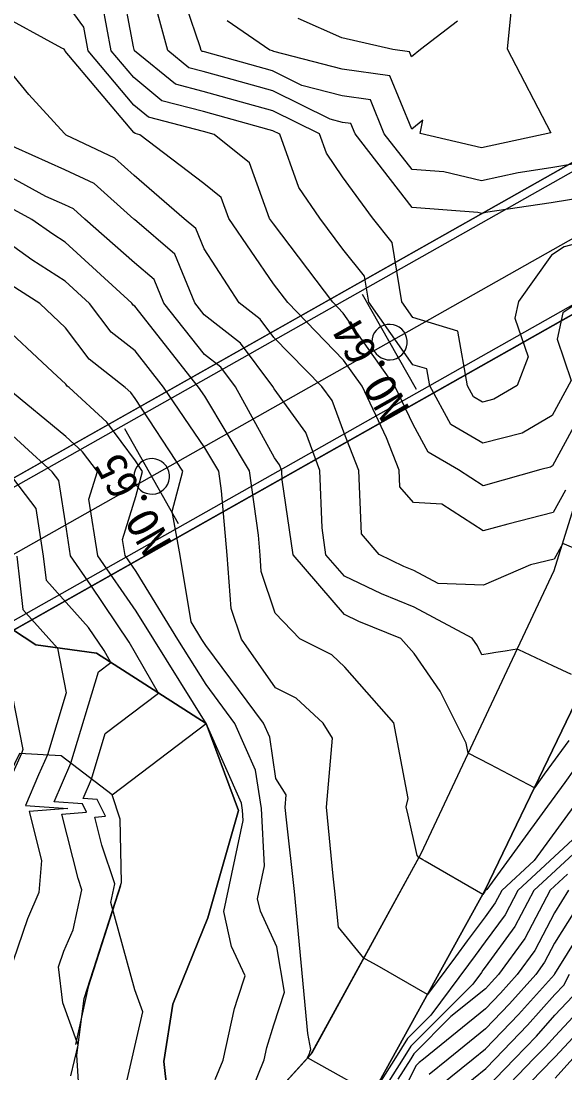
# Model space of a CAD drawing. Extents: x 42655 to 43811, y -141820 to -141156.
# Drawn here: x 42836.1 to 42875.9, y -141619.1 to -141542.1 of the extents above; entities that cross this region are included whole.
import ezdxf

# ---------------------------------------------------------------- set-up
doc = ezdxf.new("R2010")
doc.units = 0
for name, color, linetype in [('D-BMK-HTXT_1', 7, 'Continuous'), ('D-BMK_1', 7, 'Continuous'), ('D-STR-STR2トンネル', 7, 'Continuous'), ('ZE_HICN', 7, 'Continuous'), ('ZE_LWCN', 7, 'Continuous'), ('地形', 7, 'Continuous'), ('現況道路ﾊｯﾁ', 7, 'Continuous'), ('着色', 7, 'Continuous')]:
    doc.layers.add(name, color=color, linetype=linetype)

msp = doc.modelspace()

# ---------------------------------------------------------------- linework, layer by layer
at = {"layer": 'D-BMK-HTXT_1'}
for p, q in [((42865.022, -141569.047), (42861.089, -141562.081)), ((42847.607, -141578.881), (42843.674, -141571.915))]:
    msp.add_line(p, q, dxfattribs=at)
for points in [[(42861.755, -141565.564), (42861.776, -141565.796), (42861.838, -141566.021), (42861.939, -141566.231), (42862.076, -141566.419), (42862.245, -141566.58), (42862.439, -141566.709), (42862.654, -141566.8), (42862.881, -141566.852), (42863.114, -141566.862), (42863.345, -141566.831), (42863.566, -141566.759), (42863.772, -141566.649), (42863.954, -141566.503), (42864.107, -141566.328), (42864.227, -141566.128), (42864.309, -141565.91), (42864.35, -141565.68), (42864.35, -141565.447), (42864.309, -141565.218), (42864.227, -141565), (42864.107, -141564.8), (42863.954, -141564.624), (42863.772, -141564.479), (42863.566, -141564.368), (42863.345, -141564.296), (42863.114, -141564.265), (42862.881, -141564.276), (42862.654, -141564.327), (42862.439, -141564.419), (42862.245, -141564.547), (42862.076, -141564.708), (42861.939, -141564.897), (42861.838, -141565.107), (42861.776, -141565.332), (42861.755, -141565.564)], [(42844.34, -141575.398), (42844.361, -141575.63), (42844.423, -141575.855), (42844.525, -141576.065), (42844.661, -141576.254), (42844.83, -141576.415), (42845.024, -141576.543), (42845.239, -141576.635), (42845.466, -141576.687), (42845.699, -141576.697), (42845.93, -141576.666), (42846.151, -141576.594), (42846.357, -141576.483), (42846.539, -141576.338), (42846.692, -141576.162), (42846.812, -141575.962), (42846.894, -141575.744), (42846.935, -141575.515), (42846.935, -141575.282), (42846.894, -141575.052), (42846.812, -141574.834), (42846.692, -141574.634), (42846.539, -141574.459), (42846.357, -141574.313), (42846.151, -141574.203), (42845.93, -141574.131), (42845.699, -141574.1), (42845.466, -141574.11), (42845.239, -141574.162), (42845.024, -141574.254), (42844.83, -141574.382), (42844.661, -141574.543), (42844.524, -141574.732), (42844.423, -141574.942), (42844.361, -141575.166), (42844.34, -141575.398)]]:
    msp.add_lwpolyline(points, dxfattribs=at)
at = {"layer": 'D-BMK_1'}
msp.add_line((42932.715, -141526.226), (42777.191, -141614.053), dxfattribs=at)
at = {"layer": 'D-STR-STR2トンネル'}
for p, q in [((43087.053, -141433.469), (42774.793, -141609.807)), ((43087.348, -141433.992), (42775.088, -141610.33)), ((43091.527, -141441.393), (42779.268, -141617.731)), ((43091.822, -141441.915), (42779.563, -141618.253))]:
    msp.add_line(p, q, dxfattribs=at)
at = {"layer": 'ZE_HICN'}
msp.add_line((42842.734, -141598.733), (42849.632, -141593.502), dxfattribs=at)
for points in [[(42877.437, -141562.302), (42875.739, -141563.417), (42875.328, -141565.358), (42876.367, -141568.384), (42874.968, -141570.947), (42872.77, -141572.236), (42869.889, -141572.965), (42867.547, -141571.596), (42866.019, -141568.775), (42865.802, -141567.532), (42864.774, -141567.223), (42861.53, -141562.633), (42861.223, -141560.736), (42859.646, -141558.752), (42857.952, -141556.487), (42856.404, -141554.233), (42855.016, -141550.338), (42854.518, -141550.092), (42854.25, -141550.017), (42849.423, -141548.681), (42846.39, -141547.884), (42844.323, -141546.185), (42842.674, -141544.233), (42842.03, -141540.82)], [(42864.523, -141544.306), (42863.291, -141544.137), (42859.574, -141543.274), (42856.373, -141541.876)], [(42868.04, -141542.05), (42865.319, -141544.127), (42864.669, -141544.662), (42864.523, -141544.306)], [(42876.2, -141594.736), (42874.395, -141597.214), (42873.664, -141598.218), (42870.42, -141596.508), (42868.817, -141595.681), (42868.674, -141594.935), (42866.773, -141591.136), (42864.873, -141588.369), (42863.889, -141587.273), (42860.818, -141586.022), (42859.771, -141585.519), (42855.989, -141581.147), (42855.189, -141575.657), (42855.165, -141574.988), (42854.999, -141574.544), (42854.629, -141574.031), (42851.772, -141568.841), (42850.699, -141567.406), (42849.506, -141566.468), (42846.522, -141562.703), (42845.817, -141560.98), (42844.386, -141559.759), (42840.752, -141556.567), (42839.906, -141555.812), (42839.278, -141555.517), (42837.885, -141554.896), (42834.178, -141552.887)], [(42850.288, -141619.563), (42850.861, -141618.147), (42851.708, -141614.377), (42851.943, -141613.619), (42852.476, -141611.977), (42851.489, -141609.824), (42850.927, -141607.267), (42852.327, -141600.589), (42852.286, -141599.835), (42852.211, -141599.331), (42849.632, -141593.502), (42845.787, -141587.357), (42844.505, -141585.27), (42841.693, -141581.214), (42841.042, -141577.069), (42841.661, -141575.051), (42840.572, -141573.591), (42839.357, -141572.475), (42835.032, -141568.919)], [(42876.084, -141604.543), (42874.823, -141605.71), (42872.97, -141609.245), (42871.028, -141611.89), (42870.531, -141612.446), (42870.076, -141612.919), (42867.559, -141614.966), (42864.846, -141617.686), (42864.612, -141618.056), (42863.669, -141619.548)], [(42870.11, -141620.228), (42872.217, -141618.047), (42873.815, -141616.386), (42875.173, -141614.869), (42876.489, -141613.466)]]:
    msp.add_lwpolyline(points, dxfattribs=at)
at = {"layer": 'ZE_LWCN'}
for points in [[(42884.992, -141538.265), (42880.028, -141544.059), (42879.977, -141544.103), (42878.085, -141549.772), (42880.914, -141549.94), (42879.966, -141551.625), (42876.746, -141552.494), (42874.883, -141552.802), (42872.485, -141553.163), (42869.8, -141553.746), (42867.03, -141553.094), (42864.707, -141552.914), (42862.677, -141550.302), (42861.657, -141547.811), (42859.594, -141547.528), (42856.645, -141546.763), (42854.497, -141545.7), (42849.497, -141544.316), (42849.402, -141544.289), (42849.343, -141544.274), (42849.256, -141544.202), (42849.186, -141543.942), (42847.18, -141538.049)], [(42889.073, -141538.444), (42885.428, -141543.358), (42885.018, -141543.867), (42884.874, -141544.036), (42882.294, -141546.317), (42881.298, -141549.299), (42882.787, -141549.387), (42879.979, -141554.376), (42878.62, -141554.743), (42874.895, -141555.36), (42870.098, -141556.081), (42869.811, -141556.144), (42869.514, -141556.074), (42864.72, -141555.703), (42860.53, -141550.312), (42860.223, -141549.563), (42859.603, -141549.478), (42858.716, -141549.248), (42854.504, -141547.164), (42851.081, -141546.216), (42849.409, -141545.753), (42848.359, -141545.477), (42846.821, -141544.214), (42845.582, -141539.619)], [(42879.959, -141557.507), (42875.841, -141558.595), (42874.913, -141559.205), (42872.504, -141562.582), (42872.245, -141563.805), (42873.223, -141566.652), (42872.414, -141568.745), (42870.698, -141569.751), (42869.875, -141569.959), (42869.206, -141569.568), (42868.769, -141568.762), (42868.071, -141564.758), (42864.758, -141563.76), (42863.953, -141562.622), (42863.247, -141558.262), (42861.822, -141556.469), (42859.622, -141553.453), (42858.444, -141551.738), (42857.94, -141550.324), (42854.511, -141548.628), (42852.665, -141548.117), (42849.416, -141547.217), (42847.374, -141546.681), (42844.387, -141544.225), (42844.313, -141543.949), (42843.405, -141539.139)], [(42878.717, -141567.803), (42874.985, -141574.637), (42874.841, -141574.722), (42874.138, -141574.899), (42869.904, -141576.079), (42868.117, -141574.928), (42865.888, -141573.625), (42864.795, -141571.605), (42863.455, -141568.787), (42859.668, -141563.434), (42858.905, -141562.645), (42854.549, -141556.899), (42854.278, -141556.504), (42852.798, -141552.445), (42850.21, -141550.36), (42849.43, -141550.145), (42845.406, -141549.088), (42844.332, -141548.206), (42840.984, -141544.241), (42840.656, -141542.501), (42839.208, -141540.479)], [(42875.952, -141576.41), (42875.046, -141578.055), (42871.719, -141578.891), (42869.919, -141579.392), (42866.893, -141577.441), (42864.821, -141577.313), (42863.821, -141576.153), (42863.775, -141574.948), (42862.842, -141572.582), (42861.044, -141568.798), (42859.684, -141566.876), (42855.601, -141562.661), (42854.57, -141561.301), (42851.285, -141556.518), (42850.724, -141554.98), (42849.447, -141553.952), (42844.78, -141550.386), (42844.421, -141550.292), (42844.342, -141550.226), (42839.293, -141544.249), (42839.281, -141544.182), (42839.225, -141544.104), (42839.045, -141544.032), (42834.124, -141541.355)], [(42871.942, -141541.431), (42871.67, -141544.098), (42874.871, -141550.245), (42869.788, -141551.348), (42865.294, -141550.29), (42865.494, -141549.316), (42864.694, -141549.974), (42863.09, -141546.058), (42859.585, -141545.578), (42854.573, -141544.277), (42854.49, -141544.236), (42854.282, -141544.179), (42851.163, -141542.048)], [(42879.424, -141581.859), (42875.741, -141580.307), (42875.11, -141581.452), (42873.391, -141581.884), (42869.938, -141583.369), (42866.612, -141583.232), (42864.844, -141582.29), (42864.114, -141581.992), (42862.295, -141581.117), (42860.994, -141579.609), (42860.817, -141574.962), (42859.709, -141572.152), (42858.847, -141569.839), (42858.105, -141568.812), (42854.588, -141565.227), (42853.582, -141563.882), (42852.051, -141562.677), (42849.47, -141558.732), (42848.865, -141557.253), (42848.022, -141556.533), (42844.356, -141553.356), (42842.945, -141552.097), (42839.363, -141550.411), (42839.254, -141550.286), (42836.628, -141547.425), (42834.138, -141544.405)], [(42876.394, -141589.901), (42875.027, -141589.264), (42872.529, -141588.095), (42872.413, -141588.046), (42872.097, -141588.097), (42871.532, -141588.189), (42870.837, -141588.301), (42870.436, -141588.366), (42869.821, -141588.465), (42869.493, -141587.81), (42869.108, -141587.248), (42864.857, -141584.981), (42862.466, -141584.007), (42859.758, -141582.705), (42858.4, -141581.136), (42858.113, -141579.165), (42857.961, -141574.975), (42856.923, -141572.191), (42854.606, -141568.98), (42854.523, -141568.828), (42852.14, -141565.644), (42849.492, -141563.561), (42848.804, -141562.692), (42847.341, -141559.117), (42844.371, -141556.582), (42844.335, -141556.551), (42841.425, -141553.955), (42839.266, -141552.938), (42834.473, -141550.804)], [(42877.228, -141595.969), (42875.889, -141597.809), (42874.622, -141599.548), (42870.181, -141605.647), (42870.089, -141605.732), (42870.071, -141605.767), (42870.042, -141605.806), (42869.881, -141606.024), (42865.66, -141603.57), (42865.499, -141603.476), (42865.203, -141603.306), (42865.079, -141603.155), (42864.426, -141600.204), (42864.269, -141599.596), (42864.42, -141598.987), (42863.38, -141593.438), (42859.789, -141589.365), (42858.82, -141588.466), (42856.477, -141587.307), (42854.683, -141585.419), (42853.668, -141582.369), (42853.577, -141581.158), (42853.451, -141579.699), (42852.81, -141574.999), (42849.52, -141569.532), (42849.059, -141568.854), (42844.401, -141562.941), (42844.287, -141562.851), (42844.183, -141562.714), (42839.291, -141558.257), (42838.387, -141557.67), (42836.862, -141556.585), (42834.188, -141555.136)], [(42876.555, -141599.539), (42873.656, -141603.52), (42871.273, -141605.726), (42870.796, -141606.636), (42870.051, -141607.651), (42868.752, -141609.406), (42867.881, -141610.582), (42865.845, -141613.333), (42862.143, -141611.224), (42861.291, -141610.744), (42861.25, -141610.721), (42861.18, -141610.682), (42859.315, -141608.42), (42859.062, -141605.783), (42858.939, -141604.667), (42858.444, -141599.623), (42858.891, -141594.575), (42858.192, -141593.462), (42856.225, -141591.638), (42854.708, -141590.888), (42852.209, -141587.327), (42851.459, -141585.07), (42851.166, -141581.169), (42850.758, -141576.468), (42850.559, -141575.01), (42849.538, -141573.313), (42846.515, -141568.866), (42844.416, -141566.202), (42842.67, -141564.828), (42841.08, -141562.728), (42839.304, -141561.11), (42836.867, -141559.528), (42834.2, -141557.63)], [(42877.132, -141601.393), (42872.456, -141605.721), (42871.521, -141607.506), (42870.06, -141609.496), (42869.326, -141610.488), (42868.833, -141611.153), (42866.087, -141614.863), (42864.381, -141616.574), (42863.487, -141617.988), (42861.809, -141620.643), (42857.883, -141618.457), (42857.06, -141617.987), (42857.191, -141617.656), (42857.24, -141617.499), (42857.284, -141617.364), (42857.084, -141616.198), (42856.087, -141605.797), (42855.504, -141600.547), (42855.415, -141599.638), (42855.496, -141598.727), (42854.739, -141597.522), (42854.285, -141594.494), (42853.837, -141593.482), (42849.605, -141587.796), (42849.321, -141587.341), (42848.526, -141586.047), (42847.734, -141581.185), (42847.126, -141577.973), (42847.919, -141575.022), (42844.433, -141569.697), (42844.11, -141569.265), (42843.69, -141568.879), (42841.054, -141566.804), (42839.32, -141564.515), (42837.442, -141562.745), (42835.348, -141561.386)], [(42851.751, -141623.375), (42853.872, -141618.133), (42854.077, -141617.219), (42854.591, -141615.559), (42855.363, -141613.179), (42854.797, -141609.863), (42853.597, -141607.247), (42853.395, -141606.329), (42853.898, -141603.931), (42853.67, -141599.726), (42853.248, -141596.913), (42851.734, -141593.492), (42849.619, -141590.649), (42847.554, -141587.349), (42844.492, -141582.363), (42843.688, -141581.204), (42843.502, -141580.02), (42844.466, -141576.876), (42844.96, -141575.036), (42844.454, -141574.262), (42842.341, -141571.428), (42839.587, -141568.898), (42839.438, -141568.781), (42839.34, -141568.651), (42838.381, -141567.748), (42834.229, -141563.881)], [(42843.61, -141620.557), (42844.986, -141614.61), (42844.403, -141612.996), (42842.639, -141606.6), (42842.944, -141605.23), (42841.985, -141602.397), (42841.472, -141600.349), (42842.258, -141600.287), (42841.651, -141599.059), (42840.618, -141598.987), (42841.227, -141597.568), (42842.241, -141594.225), (42846.144, -141591.265), (42843.999, -141587.538), (42841.183, -141583.366), (42839.697, -141581.223), (42839.389, -141579.257), (42838.839, -141575.711), (42838.345, -141575.066), (42834.264, -141571.359)], [(42839.728, -141619.288), (42840.243, -141617.061), (42839.12, -141613.951), (42838.81, -141611.312), (42839.201, -141610.178), (42839.875, -141608.616), (42840.528, -141605.684), (42840.244, -141604.846), (42839.065, -141600.14), (42840.871, -141600), (42840.568, -141599.385), (42838.502, -141599.242), (42839.719, -141596.403), (42841.747, -141589.718), (42842.656, -141589.029), (42842.157, -141588.161), (42841.018, -141586.475), (42837.925, -141583.025), (42837.722, -141581.232), (42837.18, -141577.739), (42835.145, -141575.081)], [(42835.75, -141581.241), (42836.193, -141585.144), (42838.736, -141587.979), (42839.377, -141591.243), (42838.002, -141595.8), (42837.346, -141597.257), (42836.385, -141599.496), (42839.484, -141599.712), (42836.658, -141599.932), (42837.561, -141603.532), (42837.375, -141605.884), (42836.548, -141607.8), (42835.118, -141611.946)], [(42834.626, -141587.448), (42836.189, -141595.396), (42836.099, -141595.695), (42835.121, -141597.867)], [(42879.75, -141600.06), (42873.639, -141605.715), (42872.245, -141608.375), (42870.068, -141611.341), (42869.899, -141611.57), (42869.785, -141611.723), (42869.152, -141612.579), (42864.614, -141617.13), (42864.05, -141618.022), (42861.778, -141621.616)], [(42876.176, -141605.703), (42875.138, -141607.361), (42873.695, -141610.114), (42872.396, -141611.884), (42871.188, -141613.234), (42870.082, -141614.383), (42865.538, -141618.078), (42865.223, -141618.334), (42865.014, -141618.549), (42862.458, -141623.543)], [(42877.59, -141605.697), (42875.148, -141609.593), (42874.42, -141610.984), (42873.764, -141611.877), (42871.844, -141614.022), (42870.089, -141615.847), (42867.356, -141618.07), (42865.95, -141619.207)], [(42866.678, -141620.08), (42869.173, -141618.061), (42870.096, -141617.311), (42872.501, -141614.81), (42875.132, -141611.871), (42875.145, -141611.853), (42875.159, -141611.826), (42879.003, -141605.69)], [(42867.406, -141620.954), (42870.103, -141618.771), (42870.796, -141618.054), (42873.158, -141615.598), (42875.166, -141613.355), (42875.817, -141612.66), (42876.245, -141611.866)], [(42870.117, -141621.685), (42873.639, -141618.041), (42874.472, -141617.174), (42875.18, -141616.383), (42877.16, -141614.272)], [(42870.123, -141623.142), (42875.06, -141618.034), (42875.129, -141617.962), (42875.187, -141617.897), (42877.832, -141615.077)], [(42875.195, -141619.475), (42876.492, -141618.027)]]:
    msp.add_lwpolyline(points, dxfattribs=at)
at = {"layer": '地形'}
for points in [[(42849.542, -141623.849), (42851.871, -141623.689), (42857.399, -141617.615), (42865.364, -141603.011), (42875.126, -141582.286), (42879.7, -141567.56), (42884.865, -141548.774), (42890.476, -141535.001), (42904.088, -141518.749), (42927.38, -141502.524), (42957.635, -141477.86), (42972.865, -141465.444), (42992.716, -141449.637), (43009.337, -141439.992), (43032.561, -141430.139), (43054.789, -141429.742)], [(42848.997, -141630.72), (42853.225, -141629.019), (42860.5, -141623.012), (42870.042, -141605.732), (42880.634, -141583.758), (42885.71, -141567.43), (42888.598, -141549.639), (42895.166, -141537.825), (42907.772, -141522.776), (42930.639, -141506.846), (42961.053, -141482.053), (42976.259, -141469.657), (42995.775, -141454.117), (43011.761, -141444.84), (43033.707, -141435.529)], [(42837.144, -141587.724), (42833.01, -141585.023), (42828.127, -141581.633), (42825.396, -141579.813), (42822.086, -141579.979), (42818.971, -141579.959), (42812.466, -141582.266), (42807.219, -141583.734), (42801.763, -141583.524), (42795.677, -141582.266), (42788.122, -141580.169), (42779.518, -141576.814), (42773.432, -141571.152), (42765.248, -141564.861), (42762.52, -141558.361), (42761.68, -141552.489), (42761.051, -141548.295), (42760.673, -141546.269), (42757.757, -141542.445), (42754.295, -141538.985), (42751.379, -141536.163), (42747.279, -141532.43), (42744.09, -141530.063)], [(42846.996, -141622.369), (42846.534, -141618.245), (42847.19, -141614.061), (42849.738, -141607.719), (42851.984, -141599.859), (42849.632, -141593.502), (42841.597, -141588.35), (42837.144, -141587.724)], [(42843.437, -141605.138), (42843.326, -141600.509), (42842.734, -141598.733), (42839.012, -141595.856), (42835.966, -141595.687), (42834.853, -141597.975), (42833.967, -141601.416), (42835.243, -141612.487)], [(42843.343, -141605.381), (42840.99, -141612.773), (42840.061, -141617.011)]]:
    msp.add_lwpolyline(points, dxfattribs=at)
at = {"layer": '現況道路ﾊｯﾁ'}
for points in [[(42833.01, -141585.023), (42837.144, -141587.724), (42841.597, -141588.35), (42849.632, -141593.502), (42851.984, -141599.859), (42849.738, -141607.719), (42847.19, -141614.061), (42846.534, -141618.245), (42846.996, -141622.369), (42849.542, -141623.849), (42851.871, -141623.689), (42857.295, -141617.729), (42865.364, -141603.011), (42875.126, -141582.286), (42879.7, -141567.56), (42884.865, -141548.774), (42890.476, -141535.001), (42904.088, -141518.749), (42927.38, -141502.524), (42957.635, -141477.86), (42992.716, -141449.637), (43009.337, -141439.992), (43032.561, -141430.139), (43054.789, -141429.742)], [(43033.707, -141435.529), (43011.761, -141444.84), (42995.775, -141454.117), (42961.053, -141482.053), (42930.639, -141506.846), (42907.772, -141522.776), (42895.166, -141537.825), (42888.598, -141549.639), (42885.71, -141567.43), (42880.634, -141583.758), (42870.042, -141605.732), (42860.5, -141623.012), (42853.225, -141629.019), (42848.997, -141630.72), (42842.739, -141630.086), (42840.643, -141625.494), (42840.152, -141617.792), (42840.702, -141613.645), (42843.437, -141605.138), (42843.326, -141600.509), (42842.734, -141598.733), (42839.012, -141595.856), (42835.966, -141595.687)]]:
    msp.add_lwpolyline(points, dxfattribs=at)
at = {"layer": '着色'}
msp.add_lwpolyline([(42779.563, -141618.253), (43091.823, -141441.915), (43087.053, -141433.469), (42774.793, -141609.807)], close=True, dxfattribs=at)

# ---------------------------------------------------------------- texts
at = {"layer": 'D-BMK-HTXT_1'}
for s, p in [('NO.64', (42864.578, -141570.446)), ('NO.65', (42847.163, -141580.281))]:
    msp.add_text(s, height=2.3065, rotation=119.45336, dxfattribs=at).set_placement(p)

doc.saveas('drawing.dxf')
